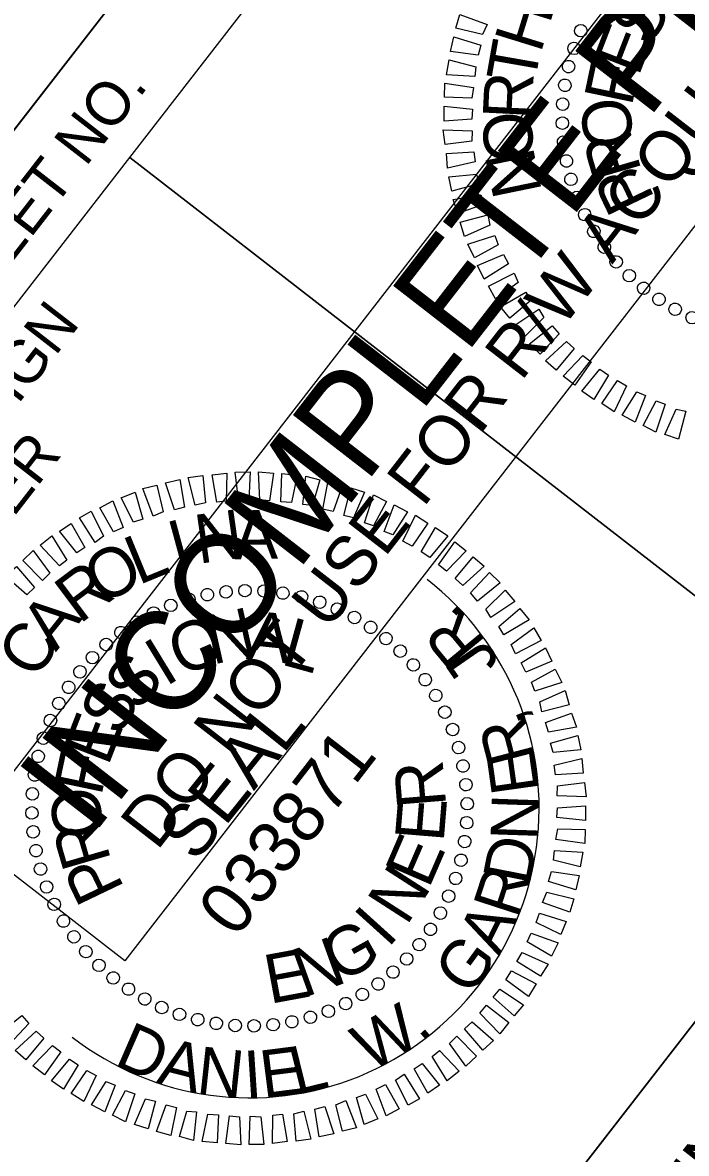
# Model space of a CAD drawing. Extents: x 2013373 to 2015284, y 444618 to 446636.
# Drawn here: x 2014375 to 2014451.4, y 446383.7 to 446513.9 of the extents above; entities that cross this region are included whole.
import ezdxf

# ---------------------------------------------------------------- set-up
doc = ezdxf.new("R2010")
doc.units = 0
for name, color, linetype in [('Old_Level_15', 7, 'Continuous'), ('Prop Conc 2ft 9in Curb and Gutter', 7, 'Continuous'), ('Prop Horizontal Alignment', 7, 'Continuous'), ('Prop Horizontal Alignment Tick Large', 7, 'Continuous'), ('Prop Paint Stripe', 7, 'Continuous'), ('Scratch_Level_3', 7, 'Continuous')]:
    doc.layers.add(name, color=color, linetype=linetype)

msp = doc.modelspace()

# ---------------------------------------------------------------- linework, layer by layer
at = {"layer": 'Old_Level_15'}
for p, q in [((2014439.25, 446512.98), (2014439.25, 446512.98)), ((2014438.44, 446510.95), (2014438.44, 446510.95)), ((2014437.84, 446508.88), (2014437.84, 446508.88)), ((2014437.44, 446506.73), (2014437.44, 446506.73)), ((2014437.18, 446504.52), (2014437.18, 446504.52)), ((2014437.1, 446502.37), (2014437.1, 446502.37)), ((2014437.27, 446500.15), (2014437.27, 446500.15)), ((2014437.58, 446498.02), (2014437.58, 446498.02)), ((2014438.13, 446495.88), (2014438.13, 446495.88)), ((2014438.79, 446493.79), (2014438.79, 446493.79)), ((2014439.72, 446491.8), (2014439.72, 446491.8)), ((2014440.75, 446489.86), (2014440.75, 446489.86)), ((2014441.98, 446488.02), (2014441.98, 446488.02)), ((2014443.36, 446486.38), (2014443.36, 446486.38)), ((2014444.84, 446484.79), (2014444.84, 446484.79)), ((2014446.49, 446483.32), (2014446.49, 446483.32)), ((2014448.26, 446482.01), (2014448.26, 446482.01)), ((2014450.14, 446480.93), (2014450.14, 446480.93)), ((2014396.25, 446448.06), (2014396.25, 446448.06)), ((2014398.39, 446448.37), (2014398.39, 446448.37)), ((2014400.61, 446448.54), (2014400.61, 446448.54)), ((2014402.76, 446448.46), (2014402.76, 446448.46)), ((2014404.97, 446448.2), (2014404.97, 446448.2)), ((2014407.12, 446447.8), (2014407.12, 446447.8)), ((2014392.02, 446446.85), (2014392.02, 446446.85)), ((2014394.11, 446447.51), (2014394.11, 446447.51)), ((2014409.19, 446447.2), (2014409.19, 446447.2)), ((2014390.04, 446445.92), (2014390.04, 446445.92)), ((2014411.22, 446446.39), (2014411.22, 446446.39)), ((2014413.2, 446445.36), (2014413.2, 446445.36)), ((2014388.1, 446444.89), (2014388.1, 446444.89)), ((2014415.09, 446444.28), (2014415.09, 446444.28)), ((2014386.26, 446443.66), (2014386.26, 446443.66)), ((2014416.85, 446442.97), (2014416.85, 446442.97)), ((2014384.62, 446442.28), (2014384.62, 446442.28)), ((2014418.5, 446441.5), (2014418.5, 446441.5)), ((2014383.02, 446440.8), (2014383.02, 446440.8)), ((2014419.99, 446439.91), (2014419.99, 446439.91)), ((2014381.56, 446439.15), (2014381.56, 446439.15)), ((2014380.25, 446437.38), (2014380.25, 446437.38)), ((2014421.37, 446438.27), (2014421.37, 446438.27)), ((2014422.6, 446436.43), (2014422.6, 446436.43)), ((2014379.17, 446435.5), (2014379.17, 446435.5)), ((2014378.14, 446433.51), (2014378.14, 446433.51)), ((2014423.63, 446434.49), (2014423.63, 446434.49)), ((2014424.56, 446432.5), (2014424.56, 446432.5)), ((2014377.32, 446431.49), (2014377.32, 446431.49)), ((2014425.21, 446430.41), (2014425.21, 446430.41)), ((2014376.73, 446429.42), (2014376.73, 446429.42)), ((2014425.77, 446428.27), (2014425.77, 446428.27)), ((2014376.33, 446427.26), (2014376.33, 446427.26)), ((2014426.07, 446426.14), (2014426.07, 446426.14)), ((2014376.07, 446425.06), (2014376.07, 446425.06)), ((2014401.12, 446423.41), (2014401.12, 446423.41)), ((2014426.25, 446423.92), (2014426.25, 446423.92)), ((2014375.99, 446422.91), (2014375.99, 446422.91)), ((2014426.16, 446421.77), (2014426.16, 446421.77)), ((2014376.16, 446420.68), (2014376.16, 446420.68)), ((2014425.91, 446419.56), (2014425.91, 446419.56)), ((2014376.46, 446418.55), (2014376.46, 446418.55)), ((2014425.5, 446417.41), (2014425.5, 446417.41)), ((2014377.02, 446416.41), (2014377.02, 446416.41)), ((2014424.91, 446415.34), (2014424.91, 446415.34)), ((2014377.68, 446414.32), (2014377.68, 446414.32)), ((2014424.1, 446413.31), (2014424.1, 446413.31)), ((2014378.6, 446412.33), (2014378.6, 446412.33)), ((2014423.06, 446411.33), (2014423.06, 446411.33)), ((2014379.63, 446410.4), (2014379.63, 446410.4)), ((2014421.98, 446409.44), (2014421.98, 446409.44)), ((2014380.86, 446408.56), (2014380.86, 446408.56)), ((2014420.68, 446407.67), (2014420.68, 446407.67)), ((2014382.25, 446406.91), (2014382.25, 446406.91)), ((2014419.21, 446406.03), (2014419.21, 446406.03)), ((2014383.73, 446405.32), (2014383.73, 446405.32)), ((2014385.38, 446403.85), (2014385.38, 446403.85)), ((2014417.61, 446404.54), (2014417.61, 446404.54)), ((2014387.15, 446402.54), (2014387.15, 446402.54)), ((2014415.97, 446403.16), (2014415.97, 446403.16)), ((2014389.03, 446401.46), (2014389.03, 446401.46)), ((2014412.19, 446400.9), (2014412.19, 446400.9)), ((2014414.13, 446401.93), (2014414.13, 446401.93)), ((2014391.01, 446400.43), (2014391.01, 446400.43)), ((2014393.04, 446399.62), (2014393.04, 446399.62)), ((2014410.21, 446399.97), (2014410.21, 446399.97)), ((2014395.11, 446399.03), (2014395.11, 446399.03)), ((2014397.27, 446398.62), (2014397.27, 446398.62)), ((2014399.47, 446398.37), (2014399.47, 446398.37)), ((2014401.62, 446398.28), (2014401.62, 446398.28)), ((2014403.84, 446398.45), (2014403.84, 446398.45)), ((2014405.98, 446398.76), (2014405.98, 446398.76)), ((2014408.12, 446399.32), (2014408.12, 446399.32))]:
    msp.add_line(p, q, dxfattribs=at)
for points in [[(2014427.97, 446512.55), (2014424.88, 446513.3), (2014425.33, 446514.86), (2014428.5, 446513.72)], [(2014427.45, 446510.17), (2014424.26, 446510.62), (2014424.66, 446512.28), (2014427.77, 446511.32)], [(2014427.08, 446507.74), (2014423.82, 446507.93), (2014424.13, 446509.64), (2014427.19, 446508.85)], [(2014426.72, 446505.23), (2014423.57, 446505.33), (2014423.62, 446506.94), (2014426.92, 446506.47)], [(2014426.74, 446502.81), (2014423.53, 446502.58), (2014423.53, 446504.29), (2014426.81, 446503.96)], [(2014426.74, 446500.28), (2014423.66, 446499.89), (2014423.44, 446501.57), (2014426.77, 446501.46)], [(2014427.11, 446497.9), (2014423.93, 446497.15), (2014423.79, 446498.84), (2014426.97, 446499.03)], [(2014427.54, 446495.36), (2014424.41, 446494.5), (2014424.06, 446496.16), (2014427.26, 446496.46)], [(2014428.13, 446493.01), (2014425.13, 446491.92), (2014424.56, 446493.56), (2014427.77, 446494.1)], [(2014428.79, 446490.6), (2014425.89, 446489.3), (2014425.39, 446490.95), (2014428.57, 446491.78)], [(2014429.75, 446488.33), (2014427.02, 446486.84), (2014426.25, 446488.39), (2014429.37, 446489.39)], [(2014430.95, 446486.13), (2014428.15, 446484.39), (2014427.38, 446485.93), (2014430.39, 446487.2)], [(2014432.08, 446483.99), (2014429.47, 446482.09), (2014428.64, 446483.56), (2014431.59, 446485.07)], [(2014433.52, 446481.93), (2014431.1, 446479.88), (2014430.01, 446481.17), (2014432.93, 446482.89)], [(2014435.02, 446479.94), (2014432.8, 446477.74), (2014431.67, 446479.06), (2014434.43, 446480.9)], [(2014436.79, 446478.07), (2014434.59, 446475.72), (2014433.37, 446476.92), (2014435.99, 446479)], [(2014438.53, 446476.4), (2014436.46, 446473.89), (2014435.22, 446474.98), (2014437.64, 446477.21)], [(2014440.47, 446474.83), (2014438.6, 446472.17), (2014437.26, 446473.21), (2014439.53, 446475.56)], [(2014442.48, 446473.33), (2014440.8, 446470.52), (2014439.4, 446471.48), (2014441.47, 446473.99)], [(2014444.56, 446472.1), (2014443.12, 446469.1), (2014441.69, 446470.03), (2014443.49, 446472.68)], [(2014446.73, 446470.98), (2014445.55, 446467.91), (2014444.03, 446468.72), (2014445.72, 446471.39)], [(2014449, 446469.99), (2014447.94, 446466.75), (2014446.46, 446467.53), (2014447.95, 446470.35)], [(2014451.38, 446469.15), (2014450.54, 446465.94), (2014448.98, 446466.46), (2014450.25, 446469.4)], [(2014397.34, 446458.68), (2014396.8, 446461.82), (2014398.48, 446462.03), (2014398.43, 446458.78)], [(2014399.83, 446458.96), (2014399.46, 446462.15), (2014401.17, 446462.16), (2014401.05, 446458.9)], [(2014402.29, 446458.95), (2014402.13, 446462.17), (2014403.86, 446462.03), (2014403.41, 446458.84)], [(2014392.46, 446457.78), (2014391.42, 446460.92), (2014393.09, 446461.28), (2014393.6, 446458.1)], [(2014394.85, 446458.33), (2014394.05, 446461.54), (2014395.73, 446461.75), (2014396.02, 446458.62)], [(2014404.71, 446458.72), (2014404.83, 446461.98), (2014406.6, 446461.81), (2014405.93, 446458.66)], [(2014407.24, 446458.4), (2014407.58, 446461.68), (2014409.2, 446461.25), (2014408.36, 446458.29)], [(2014409.55, 446457.87), (2014410.18, 446461.12), (2014411.84, 446460.65), (2014410.73, 446457.59)], [(2014387.76, 446456.36), (2014386.33, 446459.18), (2014387.92, 446459.84), (2014388.81, 446456.74)], [(2014390.02, 446457.08), (2014388.8, 446460.24), (2014390.43, 446460.62), (2014391.17, 446457.58)], [(2014411.96, 446457.14), (2014412.8, 446460.35), (2014414.37, 446459.83), (2014413.1, 446456.89)], [(2014414.35, 446456.3), (2014415.4, 446459.54), (2014416.89, 446458.76), (2014415.39, 446455.94)], [(2014385.44, 446455.25), (2014383.87, 446458.04), (2014385.38, 446458.84), (2014386.55, 446455.78)], [(2014416.61, 446455.31), (2014417.79, 446458.38), (2014419.32, 446457.57), (2014417.63, 446454.9)], [(2014383.31, 446454.05), (2014381.52, 446456.89), (2014382.86, 446457.63), (2014384.29, 446454.75)], [(2014418.79, 446454.19), (2014420.22, 446457.19), (2014421.66, 446456.26), (2014419.86, 446453.61)], [(2014381.22, 446452.83), (2014379.23, 446455.32), (2014380.57, 446456.24), (2014382.14, 446453.44)], [(2014420.87, 446452.96), (2014422.54, 446455.77), (2014423.95, 446454.81), (2014421.88, 446452.3)], [(2014379.23, 446451.33), (2014376.97, 446453.72), (2014378.33, 446454.81), (2014380.08, 446452.01)], [(2014377.24, 446449.65), (2014374.98, 446451.97), (2014376.19, 446453.12), (2014378.09, 446450.51)], [(2014422.87, 446451.46), (2014424.75, 446454.12), (2014426.09, 446453.08), (2014423.82, 446450.73)], [(2014424.82, 446449.89), (2014426.89, 446452.4), (2014428.13, 446451.31), (2014425.7, 446449.08)], [(2014375.45, 446448), (2014373, 446450.15), (2014374.25, 446451.27), (2014376.34, 446448.83)], [(2014426.56, 446448.22), (2014428.76, 446450.57), (2014429.98, 446449.37), (2014427.36, 446447.29)], [(2014428.33, 446446.35), (2014430.55, 446448.55), (2014431.68, 446447.23), (2014428.91, 446445.39)], [(2014429.83, 446444.36), (2014432.24, 446446.41), (2014433.33, 446445.12), (2014430.41, 446443.4)], [(2014431.27, 446442.3), (2014433.88, 446444.2), (2014434.7, 446442.73), (2014431.76, 446441.22)], [(2014432.39, 446440.16), (2014435.2, 446441.9), (2014435.96, 446440.36), (2014432.95, 446439.09)], [(2014433.6, 446437.96), (2014436.33, 446439.45), (2014437.1, 446437.9), (2014433.98, 446436.9)], [(2014434.56, 446435.69), (2014437.46, 446436.99), (2014437.95, 446435.34), (2014434.78, 446434.51)], [(2014435.22, 446433.28), (2014438.22, 446434.37), (2014438.78, 446432.74), (2014435.57, 446432.19)], [(2014435.8, 446430.93), (2014438.94, 446431.79), (2014439.29, 446430.13), (2014436.08, 446429.83)], [(2014436.23, 446428.39), (2014439.41, 446429.14), (2014439.56, 446427.45), (2014436.37, 446427.26)], [(2014436.6, 446426.01), (2014439.69, 446426.4), (2014439.9, 446424.72), (2014436.57, 446424.83)], [(2014436.6, 446423.48), (2014439.82, 446423.71), (2014439.82, 446422), (2014436.53, 446422.33)], [(2014436.62, 446421.06), (2014439.77, 446420.96), (2014439.73, 446419.35), (2014436.42, 446419.82)], [(2014436.26, 446418.55), (2014439.53, 446418.36), (2014439.21, 446416.65), (2014436.15, 446417.44)], [(2014435.89, 446416.12), (2014439.09, 446415.67), (2014438.69, 446414.01), (2014435.57, 446414.97)], [(2014435.37, 446413.74), (2014438.46, 446412.99), (2014438.02, 446411.43), (2014434.85, 446412.57)], [(2014434.51, 446411.31), (2014437.58, 446410.38), (2014436.99, 446408.88), (2014434.14, 446410.27)], [(2014433.55, 446409.02), (2014436.68, 446407.92), (2014435.92, 446406.36), (2014433.1, 446408.03)], [(2014432.51, 446406.78), (2014435.53, 446405.45), (2014434.64, 446404.06), (2014431.9, 446405.74)], [(2014431.28, 446404.7), (2014434.14, 446403.18), (2014433.26, 446401.71), (2014430.66, 446403.66)], [(2014429.94, 446402.57), (2014432.67, 446400.78), (2014431.61, 446399.51), (2014429.17, 446401.66)], [(2014375.67, 446398.6), (2014373.47, 446396.25), (2014372.25, 446397.45), (2014374.88, 446399.53)], [(2014428.43, 446400.71), (2014431, 446398.72), (2014429.95, 446397.44), (2014427.66, 446399.79)], [(2014426.78, 446398.82), (2014429.23, 446396.67), (2014427.98, 446395.55), (2014425.89, 446398)], [(2014377.42, 446396.93), (2014375.35, 446394.42), (2014374.1, 446395.51), (2014376.53, 446397.75)], [(2014425, 446397.17), (2014427.25, 446394.86), (2014426.04, 446393.71), (2014424.14, 446396.32)], [(2014379.36, 446395.36), (2014377.49, 446392.7), (2014376.14, 446393.74), (2014378.41, 446396.09)], [(2014381.37, 446393.87), (2014379.69, 446391.05), (2014378.29, 446392.02), (2014380.36, 446394.52)], [(2014423, 446395.5), (2014425.26, 446393.11), (2014423.9, 446392.01), (2014422.16, 446394.82)], [(2014383.45, 446392.63), (2014382.01, 446389.64), (2014380.57, 446390.56), (2014382.38, 446393.21)], [(2014421.01, 446394), (2014423, 446391.5), (2014421.66, 446390.59), (2014420.09, 446393.38)], [(2014385.62, 446391.52), (2014384.44, 446388.45), (2014382.91, 446389.25), (2014384.61, 446391.92)], [(2014418.92, 446392.77), (2014420.71, 446389.93), (2014419.38, 446389.19), (2014417.94, 446392.08)], [(2014387.88, 446390.52), (2014386.83, 446387.29), (2014385.34, 446388.06), (2014386.84, 446390.89)], [(2014414.48, 446390.46), (2014415.9, 446387.65), (2014414.31, 446386.98), (2014413.42, 446390.08)], [(2014416.79, 446391.57), (2014418.36, 446388.78), (2014416.86, 446387.98), (2014415.69, 446391.04)], [(2014390.27, 446389.68), (2014389.43, 446386.48), (2014387.87, 446386.99), (2014389.13, 446389.93)], [(2014392.68, 446388.95), (2014392.06, 446385.7), (2014390.39, 446386.17), (2014391.5, 446389.23)], [(2014412.21, 446389.75), (2014413.43, 446386.59), (2014411.81, 446386.2), (2014411.07, 446389.25)], [(2014394.99, 446388.43), (2014394.66, 446385.14), (2014393.03, 446385.58), (2014393.87, 446388.53)], [(2014397.53, 446388.11), (2014397.4, 446384.85), (2014395.64, 446385.02), (2014396.31, 446388.17)], [(2014399.94, 446387.88), (2014400.1, 446384.65), (2014398.37, 446384.79), (2014398.82, 446387.98)], [(2014402.4, 446387.87), (2014402.77, 446384.67), (2014401.06, 446384.67), (2014401.18, 446387.93)], [(2014404.9, 446388.15), (2014405.44, 446385.01), (2014403.75, 446384.79), (2014403.81, 446388.04)], [(2014407.38, 446388.5), (2014408.18, 446385.28), (2014406.5, 446385.07), (2014406.21, 446388.21)], [(2014409.77, 446389.05), (2014410.81, 446385.9), (2014409.15, 446385.55), (2014408.64, 446388.73)]]:
    msp.add_lwpolyline(points, close=True, dxfattribs=at)
for centre, major_axis in [((2014439.28, 446513), (-0.659, 0.29)), ((2014438.49, 446510.96), (-0.682, 0.232)), ((2014437.87, 446508.86), (-0.699, 0.172)), ((2014437.44, 446506.71), (-0.712, 0.11)), ((2014437.2, 446504.54), (-0.718, 0.048)), ((2014437.15, 446502.35), (-0.72, -0.015)), ((2014437.3, 446500.17), (-0.716, -0.078)), ((2014437.63, 446498), (-0.706, -0.14)), ((2014438.15, 446495.88), (-0.691, -0.201)), ((2014438.85, 446493.81), (-0.671, -0.26)), ((2014439.73, 446491.8), (-0.646, -0.318)), ((2014440.78, 446489.88), (-0.616, -0.373)), ((2014441.99, 446488.06), (-0.581, -0.425)), ((2014443.36, 446486.36), (-0.542, -0.474)), ((2014444.87, 446484.78), (-0.498, -0.52)), ((2014446.52, 446483.33), (-0.451, -0.561)), ((2014448.28, 446482.04), (-0.4, -0.598)), ((2014450.15, 446480.9), (-0.347, -0.631)), ((2014452.11, 446479.93), (-0.29, -0.659)), ((2014398.41, 446448.35), (-0.078, 0.716)), ((2014400.59, 446448.49), (-0.015, 0.72)), ((2014402.78, 446448.44), (0.048, 0.718)), ((2014394.12, 446447.5), (-0.201, 0.691)), ((2014396.24, 446448.01), (-0.14, 0.706)), ((2014404.95, 446448.2), (0.11, 0.712)), ((2014407.1, 446447.77), (0.172, 0.699)), ((2014409.2, 446447.15), (0.232, 0.682)), ((2014390.04, 446445.91), (-0.318, 0.646)), ((2014392.04, 446446.79), (-0.26, 0.671)), ((2014411.24, 446446.36), (0.29, 0.659)), ((2014388.12, 446444.86), (-0.373, 0.616)), ((2014413.2, 446445.39), (0.347, 0.631)), ((2014386.3, 446443.65), (-0.425, 0.581)), ((2014415.07, 446444.25), (0.4, 0.598)), ((2014384.6, 446442.28), (-0.474, 0.542)), ((2014416.83, 446442.96), (0.451, 0.561)), ((2014383.01, 446440.77), (-0.52, 0.498)), ((2014418.47, 446441.52), (0.498, 0.52)), ((2014381.57, 446439.13), (-0.561, 0.451)), ((2014419.99, 446439.93), (0.542, 0.474)), ((2014421.35, 446438.23), (0.581, 0.425)), ((2014380.27, 446437.36), (-0.598, 0.4)), ((2014379.14, 446435.49), (-0.631, 0.347)), ((2014422.57, 446436.41), (0.616, 0.373)), ((2014423.62, 446434.49), (0.646, 0.318)), ((2014378.17, 446433.53), (-0.659, 0.29)), ((2014377.37, 446431.49), (-0.682, 0.232)), ((2014424.5, 446432.48), (0.671, 0.26)), ((2014425.2, 446430.41), (0.691, 0.201)), ((2014376.76, 446429.39), (-0.699, 0.172)), ((2014425.72, 446428.29), (0.706, 0.14)), ((2014376.33, 446427.25), (-0.712, 0.11)), ((2014426.05, 446426.12), (0.716, 0.078)), ((2014376.09, 446425.07), (-0.718, 0.048)), ((2014426.19, 446423.94), (0.72, 0.015)), ((2014376.04, 446422.88), (-0.72, -0.015)), ((2014426.14, 446421.75), (0.718, -0.048)), ((2014376.18, 446420.7), (-0.716, -0.078)), ((2014425.9, 446419.58), (0.712, -0.11)), ((2014376.51, 446418.54), (-0.706, -0.14)), ((2014425.47, 446417.43), (0.699, -0.172)), ((2014377.03, 446416.41), (-0.691, -0.201)), ((2014377.73, 446414.34), (-0.671, -0.26)), ((2014424.86, 446415.33), (0.682, -0.232)), ((2014424.06, 446413.29), (0.659, -0.29)), ((2014378.61, 446412.34), (-0.646, -0.318)), ((2014379.67, 446410.42), (-0.616, -0.373)), ((2014423.1, 446411.33), (0.631, -0.347)), ((2014421.96, 446409.46), (0.598, -0.4)), ((2014380.88, 446408.6), (-0.581, -0.425)), ((2014382.25, 446406.89), (-0.542, -0.474)), ((2014420.66, 446407.7), (0.561, -0.451)), ((2014383.76, 446405.31), (-0.498, -0.52)), ((2014419.22, 446406.05), (0.52, -0.498)), ((2014417.64, 446404.54), (0.474, -0.542)), ((2014385.4, 446403.86), (-0.451, -0.561)), ((2014415.93, 446403.17), (0.425, -0.581)), ((2014387.17, 446402.57), (-0.4, -0.598)), ((2014389.04, 446401.43), (-0.347, -0.631)), ((2014414.11, 446401.96), (0.373, -0.616)), ((2014391, 446400.46), (-0.29, -0.659)), ((2014410.19, 446400.03), (0.26, -0.671)), ((2014412.19, 446400.91), (0.318, -0.646)), ((2014393.04, 446399.67), (-0.232, -0.682)), ((2014395.14, 446399.06), (-0.172, -0.699)), ((2014405.99, 446398.81), (0.14, -0.706)), ((2014408.12, 446399.33), (0.201, -0.691)), ((2014397.28, 446398.63), (-0.11, -0.712)), ((2014399.46, 446398.39), (-0.048, -0.718)), ((2014401.64, 446398.34), (0.015, -0.72)), ((2014403.83, 446398.48), (0.078, -0.716))]:
    msp.add_ellipse(centre, major_axis=major_axis, ratio=0.999708, dxfattribs=at)
at = {"layer": 'Prop Horizontal Alignment'}
for p, q in [((2014316.13, 446427), (2014438.73, 446585.08)), ((2014387.32, 446498.4), (2014476.18, 446429.49))]:
    msp.add_line(p, q, dxfattribs=at)
for points in [[(2014296.33, 446442.35), (2014418.93, 446600.43), (2014438.73, 446585.08), (2014316.13, 446427)], [(2014387.32, 446498.4), (2014448.6, 446577.42), (2014537.5, 446508.48), (2014476.22, 446429.46)], [(2014326.01, 446419.34), (2014387.32, 446498.4), (2014476.22, 446429.46), (2014414.9, 446350.4)]]:
    msp.add_lwpolyline(points, close=True, dxfattribs=at)
at = {"layer": 'Prop Horizontal Alignment Tick Large'}
msp.add_lwpolyline([(2014386.73, 446405.85), (2014368.16, 446420.25), (2014458.24, 446536.41), (2014476.81, 446522.01)], close=True, dxfattribs=at)
at = {"layer": 'Prop Paint Stripe'}
msp.add_arc((2014401.12, 446423.41), 33.36, 232.2051, 52.2051, dxfattribs=at)
at = {"layer": 'Scratch_Level_3'}
msp.add_line((2014414.89, 446350.41), (2014537.49, 446508.49), dxfattribs=at)

# ---------------------------------------------------------------- texts
at = {"layer": 'Old_Level_15'}
for s, height, rotation, p in [('S', 5.64, 59.4607, (2014447.2, 446510.99)), ('H', 5.64, 72.8246, (2014434.64, 446510.3)), ('E', 5.64, 68.8162, (2014445.91, 446507.62)), ('T', 5.64, 80.0249, (2014433.95, 446506.72)), ('F', 5.64, 78.1721, (2014445.14, 446504.17)), ('R', 5.64, 87.2256, (2014433.6, 446502.68)), ('O', 5.64, 96.8863, (2014445.45, 446499.76)), ('O', 5.64, 94.4268, (2014433.94, 446498.05)), ('R', 5.64, 106.2448, (2014446.31, 446496.87)), ('N', 5.64, 101.6286, (2014434.82, 446494.46)), ('P', 5.64, 115.604, (2014447.86, 446493.65)), ('N', 5.64, 8.024, (2014395.24, 446451.57)), ('A', 5.64, 0.8223, (2014399.38, 446452.09)), ('I', 5.64, 15.2252, (2014392.7, 446450.82)), ('L', 5.64, 22.426, (2014388.32, 446449.09)), ('O', 5.64, 29.6263, (2014384.16, 446446.75)), ('R', 5.64, 36.8262, (2014381.52, 446444.56)), ('A', 5.64, 51.2254, (2014378.78, 446441.36)), ('N', 5.64, 12.6817, (2014396.85, 446439.94)), ('O', 5.64, 22.0386, (2014393.22, 446438.52)), ('A', 5.64, 353.9654, (2014400.65, 446440.6)), ('L', 5.64, 344.606, (2014404.58, 446440.03)), ('C', 5.64, 58.425, (2014376.6, 446438.06)), ('I', 5.64, 31.3947, (2014391.44, 446437.37)), ('S', 5.64, 50.1055, (2014388.25, 446434.4)), ('S', 5.64, 59.4607, (2014386.09, 446431.53)), ('E', 5.64, 68.8162, (2014384.8, 446428.16)), ('SEAL', 5.998, 51.2051, (2014394.9, 446417.03)), ('F', 5.64, 78.1721, (2014384.03, 446424.71)), ('R', 5.64, 94.6865, (2014423.78, 446423.68)), ('O', 5.64, 96.8863, (2014384.33, 446420.29)), ('E', 5.64, 85.3292, (2014423.47, 446419.43)), ('R', 5.64, 106.2448, (2014385.2, 446417.41)), ('E', 5.64, 66.6169, (2014421.76, 446414.05)), ('P', 5.64, 115.604, (2014386.75, 446414.18)), ('N', 5.64, 57.2615, (2014419.2, 446409.77)), ('I', 5.64, 47.9063, (2014417.03, 446407.21)), ('G', 5.64, 29.1953, (2014411.51, 446403.2)), ('N', 5.64, 19.8391, (2014407.4, 446401.58)), ('E', 5.64, 10.482, (2014403.43, 446400.86))]:
    msp.add_text(s, height=height, rotation=rotation, dxfattribs=at).set_placement(p)
at = {"layer": 'Prop Conc 2ft 9in Curb and Gutter'}
for s, height, rotation, p in [('R', 5.5, 129.5592, (2014428.53, 446442.61)), ('.', 5.5, 136.4856, (2014426.02, 446445.77)), ('J', 5.5, 124.6906, (2014430.06, 446440.21)), ('R', 5.5, 104.5839, (2014434.08, 446429.24)), (',', 5.5, 111.5103, (2014433.13, 446433.17)), ('033871', 5.998, 52.2051, (2014399.54, 446408.31)), ('E', 5.5, 98.0009, (2014434.53, 446425.42)), ('N', 5.5, 88.0692, (2014434.37, 446419.63)), ('D', 5.5, 78.9246, (2014433.35, 446414.39)), ('R', 5.5, 71.9981, (2014432.02, 446410.57)), ('A', 5.5, 63.8123, (2014429.88, 446406.3)), ('G', 5.5, 53.8806, (2014426.5, 446401.59)), ('W', 5.5, 29.0943, (2014415.01, 446392.96)), ('D', 5.5, 336.4733, (2014385.36, 446393.88)), ('.', 5.5, 40.7003, (2014420.85, 446396.38)), ('A', 5.5, 345.6179, (2014390.25, 446391.76)), ('N', 5.5, 353.8037, (2014394.87, 446390.53)), ('E', 5.5, 7.2559, (2014402.69, 446389.98)), ('L', 5.5, 13.8389, (2014406.51, 446390.38)), ('I', 5.5, 3.7355, (2014400.63, 446389.95))]:
    msp.add_text(s, height=height, rotation=rotation, dxfattribs=at).set_placement(p)
at = {"layer": 'Prop Horizontal Alignment'}
for s, height, p in [('R/W SHEET NO.', 5.0001, (2014358.33, 446466.4)), ('ROADWAY DESIGN', 5.0001, (2014343.66, 446430.2)), ('ENGINEER', 5, (2014358.18, 446436.59))]:
    msp.add_text(s, height=height, rotation=52.2051, dxfattribs=at).set_placement(p)
at = {"layer": 'Prop Horizontal Alignment Tick Large'}
for s, height, p in [('INCOMPLETE PLANS', 11.52, (2014382.97, 446420.09)), ('DO NOT USE FOR R/W ACQUISITION', 5.76, (2014390.45, 446418.4))]:
    msp.add_text(s, height=height, rotation=52.2051, dxfattribs=at).set_placement(p)
at = {"layer": 'Scratch_Level_3'}
for s, p in [('DOCUMENT NOT CONSIDERED FINAL', (2014433.14, 446350.97)), ('UNLESS ALL SIGNATURES COMPLETED', (2014437.74, 446340.15))]:
    msp.add_text(s, height=6.124, rotation=52.2051, dxfattribs=at).set_placement(p)

doc.saveas('drawing.dxf')
